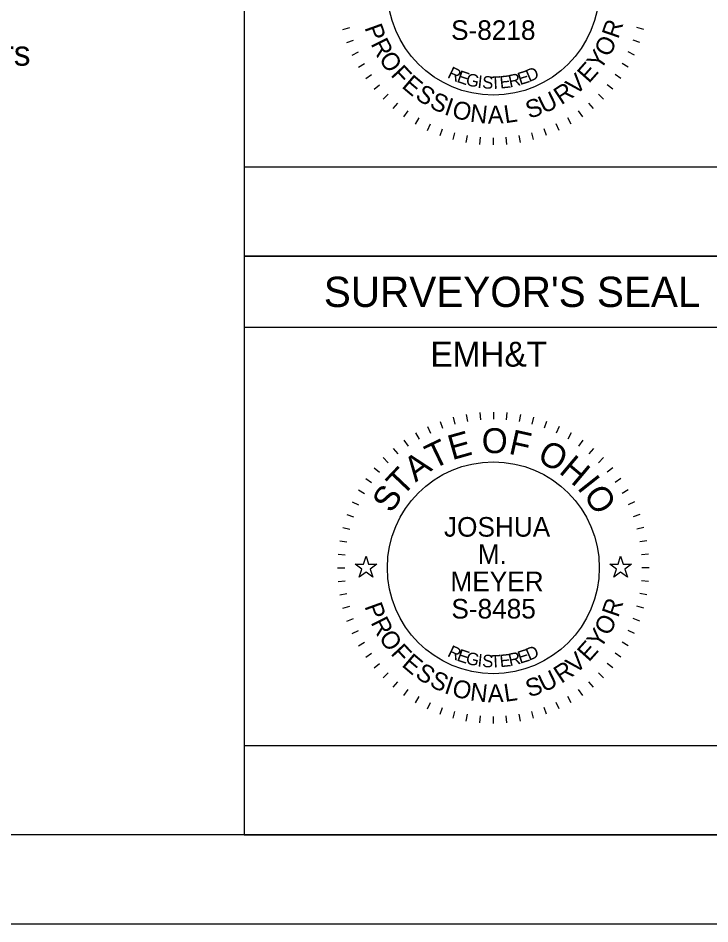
# Model space of a CAD drawing. Extents: x 0 to 34, y -5.4 to 22.
# Drawn here: x 27.93 to 31.82, y 0 to 5.09 of the extents above; entities that cross this region are included whole.
import ezdxf

# ---------------------------------------------------------------- set-up
doc = ezdxf.new("R2010")
doc.units = 0
for name, color, linetype in [('Default', 7, 'Continuous'), ('SH_Border', 7, 'Continuous'), ('SH_Cut_Line', 7, 'Continuous'), ('SH_Data', 7, 'Continuous'), ('SH_Text', 7, 'Continuous')]:
    doc.layers.add(name, color=color, linetype=linetype)

msp = doc.modelspace()

# ---------------------------------------------------------------- linework, layer by layer
at = {"layer": 'Default'}
for points in [[(29.8236, 2.02), (29.8705, 2.02), (29.885, 2.0645), (29.8995, 2.02), (29.9464, 2.02), (29.9085, 1.9924), (29.923, 1.9478), (29.885, 1.9754), (29.847, 1.9478), (29.8615, 1.9924)], [(31.2536, 2.02), (31.3005, 2.02), (31.315, 2.0645), (31.3295, 2.02), (31.3764, 2.02), (31.3385, 1.9924), (31.353, 1.9478), (31.315, 1.9754), (31.277, 1.9478), (31.2915, 1.9924)]]:
    msp.add_lwpolyline(points, close=True, dxfattribs=at)
at = {"layer": 'SH_Border'}
msp.add_lwpolyline([(1.5, 21.5), (33.5, 21.5), (33.5, 0.5), (1.5, 0.5)], close=True, dxfattribs=at)
at = {"layer": 'SH_Cut_Line'}
msp.add_lwpolyline([(0, 0), (34, 0), (34, 22), (0, 22)], close=True, dxfattribs=at)
at = {"layer": 'SH_Data'}
for p, q in [((29.2, 7), (29.2, 3.75)), ((29.7548, 5.0235), (29.7935, 5.0339)), ((31.4452, 5.0235), (31.4065, 5.0339)), ((29.7778, 4.9507), (29.8154, 4.9644)), ((31.4222, 4.9507), (31.3846, 4.9644)), ((29.807, 4.8802), (29.8432, 4.8971)), ((31.393, 4.8802), (31.3568, 4.8971)), ((29.8422, 4.8125), (29.8769, 4.8325)), ((31.3578, 4.8125), (31.3231, 4.8325)), ((29.8832, 4.7481), (29.916, 4.7711)), ((31.3168, 4.7481), (31.284, 4.7711)), ((29.9297, 4.6876), (29.9604, 4.7133)), ((31.2703, 4.6876), (31.2396, 4.7133)), ((29.9813, 4.6313), (30.0096, 4.6596)), ((31.2187, 4.6313), (31.1904, 4.6596)), ((30.0376, 4.5797), (30.0633, 4.6104)), ((31.1624, 4.5797), (31.1367, 4.6104)), ((30.0981, 4.5332), (30.1211, 4.566)), ((31.1019, 4.5332), (31.0789, 4.566)), ((30.1625, 4.4922), (30.1825, 4.5269)), ((30.2302, 4.457), (30.2471, 4.4932)), ((30.9698, 4.457), (30.9529, 4.4932)), ((31.0375, 4.4922), (31.0175, 4.5269)), ((30.3007, 4.4278), (30.3144, 4.4654)), ((30.3735, 4.4048), (30.3839, 4.4435)), ((30.4481, 4.3883), (30.455, 4.4277)), ((30.7519, 4.3883), (30.745, 4.4277)), ((30.8265, 4.4048), (30.8161, 4.4435)), ((30.8993, 4.4278), (30.8856, 4.4654)), ((30.5237, 4.3783), (30.5272, 4.4182)), ((30.6, 4.375), (30.6, 4.415)), ((30.6763, 4.3783), (30.6728, 4.4182)), ((32, 3.75), (29.2, 3.75)), ((29.2, 3.75), (29.2, 0.5)), ((32, 3.75), (29.2, 3.75)), ((32, 3.35), (29.2, 3.35)), ((30.4481, 2.8617), (30.455, 2.8223)), ((30.5237, 2.8717), (30.5272, 2.8318)), ((30.6, 2.875), (30.6, 2.835)), ((30.6763, 2.8717), (30.6728, 2.8318)), ((30.7519, 2.8617), (30.745, 2.8223)), ((30.3007, 2.8222), (30.3144, 2.7846)), ((30.3735, 2.8452), (30.3839, 2.8065)), ((30.8265, 2.8452), (30.8161, 2.8065)), ((30.8993, 2.8222), (30.8856, 2.7846)), ((30.1625, 2.7578), (30.1825, 2.7231)), ((30.2302, 2.793), (30.2471, 2.7568)), ((30.9698, 2.793), (30.9529, 2.7568)), ((31.0375, 2.7578), (31.0175, 2.7231)), ((30.0981, 2.7168), (30.1211, 2.684)), ((31.1019, 2.7168), (31.0789, 2.684)), ((30.0376, 2.6703), (30.0633, 2.6396)), ((31.1624, 2.6703), (31.1367, 2.6396)), ((29.9813, 2.6187), (30.0096, 2.5904)), ((31.2187, 2.6187), (31.1904, 2.5904)), ((29.9297, 2.5624), (29.9604, 2.5367)), ((31.2703, 2.5624), (31.2396, 2.5367)), ((29.8832, 2.5019), (29.916, 2.4789)), ((31.3168, 2.5019), (31.284, 2.4789)), ((29.8422, 2.4375), (29.8769, 2.4175)), ((31.3578, 2.4375), (31.3231, 2.4175)), ((29.807, 2.3698), (29.8432, 2.3529)), ((31.393, 2.3698), (31.3568, 2.3529)), ((29.7778, 2.2993), (29.8154, 2.2856)), ((31.4222, 2.2993), (31.3846, 2.2856)), ((29.7548, 2.2265), (29.7935, 2.2161)), ((31.4452, 2.2265), (31.4065, 2.2161)), ((29.7383, 2.1519), (29.7777, 2.145)), ((31.4617, 2.1519), (31.4223, 2.145)), ((29.7283, 2.0763), (29.7682, 2.0728)), ((31.4717, 2.0763), (31.4318, 2.0728)), ((29.725, 2), (29.765, 2)), ((31.475, 2), (31.435, 2)), ((29.7283, 1.9237), (29.7682, 1.9272)), ((31.4717, 1.9237), (31.4318, 1.9272)), ((29.7383, 1.8481), (29.7777, 1.855)), ((31.4617, 1.8481), (31.4223, 1.855)), ((29.7548, 1.7735), (29.7935, 1.7839)), ((31.4452, 1.7735), (31.4065, 1.7839)), ((29.7778, 1.7007), (29.8154, 1.7144)), ((31.4222, 1.7007), (31.3846, 1.7144)), ((29.807, 1.6302), (29.8432, 1.6471)), ((31.393, 1.6302), (31.3568, 1.6471)), ((29.8422, 1.5625), (29.8769, 1.5825)), ((31.3578, 1.5625), (31.3231, 1.5825)), ((29.8832, 1.4981), (29.916, 1.5211)), ((31.3168, 1.4981), (31.284, 1.5211)), ((29.9297, 1.4376), (29.9604, 1.4633)), ((31.2703, 1.4376), (31.2396, 1.4633)), ((29.9813, 1.3813), (30.0096, 1.4096)), ((31.2187, 1.3813), (31.1904, 1.4096)), ((30.0376, 1.3297), (30.0633, 1.3604)), ((31.1624, 1.3297), (31.1367, 1.3604)), ((30.0981, 1.2832), (30.1211, 1.316)), ((30.1625, 1.2422), (30.1825, 1.2769)), ((31.0375, 1.2422), (31.0175, 1.2769)), ((31.1019, 1.2832), (31.0789, 1.316)), ((30.2302, 1.207), (30.2471, 1.2432)), ((30.9698, 1.207), (30.9529, 1.2432)), ((30.3007, 1.1778), (30.3144, 1.2154)), ((30.3735, 1.1548), (30.3839, 1.1935)), ((30.4481, 1.1383), (30.455, 1.1777)), ((30.7519, 1.1383), (30.745, 1.1777)), ((30.8265, 1.1548), (30.8161, 1.1935)), ((30.8993, 1.1778), (30.8856, 1.2154)), ((30.5237, 1.1283), (30.5272, 1.1682)), ((30.6, 1.125), (30.6, 1.165)), ((30.6763, 1.1283), (30.6728, 1.1682)), ((32, 0.5), (29.2, 0.5)), ((32, 0.5), (29.2, 0.5))]:
    msp.add_line(p, q, dxfattribs=at)
for points in [[(32, 3.75), (32, 4.25), (29.2, 4.25), (29.2, 3.75)], [(32, 0.5), (32, 1), (29.2, 1), (29.2, 0.5)]]:
    msp.add_lwpolyline(points, close=True, dxfattribs=at)
for centre in [(30.6, 5.25), (30.6, 2)]:
    msp.add_circle(centre, 0.595, dxfattribs=at)

# ---------------------------------------------------------------- texts
for s, height, rotation, p in [('P', 0.1, 289.7431, (29.8753, 5.0341)), ('R', 0.1, 70.983, (31.3009, 4.9667)), ('R', 0.1, 296.9802, (29.9093, 4.9427)), ('O', 0.1, 62.7428, (31.2501, 4.8633)), ('O', 0.1, 304.7158, (29.9532, 4.8579)), ('Y', 0.1, 55.5058, (31.2, 4.79)), ('E', 0.1, 48.2687, (31.1366, 4.7173)), ('F', 0.1, 312.956, (30.0192, 4.7658)), ('R', 0.07, 334.487, (30.3375, 4.7551)), ('E', 0.07, 341.04, (30.3906, 4.7301)), ('E', 0.07, 17.6836, (30.7498, 4.7102)), ('D', 0.07, 23.3052, (30.801, 4.727)), ('V', 0.1, 41.0316, (31.0615, 4.6507)), ('E', 0.1, 319.6885, (30.0808, 4.7004)), ('G', 0.07, 347.4752, (30.4414, 4.7118)), ('I', 0.07, 353.7858, (30.5091, 4.6968)), ('S', 0.07, 356.8926, (30.5358, 4.6929)), ('T', 0.07, 3.0061, (30.5857, 4.6887)), ('E', 0.07, 6.0117, (30.6389, 4.6912)), ('R', 0.07, 11.9184, (30.6925, 4.6974)), ('S', 0.1, 326.9255, (30.1554, 4.6385)), ('R', 0.1, 33.296, (30.9815, 4.5973)), ('S', 0.1, 334.1626, (30.236, 4.5874)), ('I', 0.1, 341.3997, (30.3191, 4.5479)), ('S', 0.1, 18.3234, (30.8005, 4.5211)), ('U', 0.1, 25.5604, (30.8833, 4.5486)), ('O', 0.1, 345.1351, (30.3618, 4.5321)), ('N', 0.1, 353.3752, (30.466, 4.5055)), ('A', 0.1, 1.1108, (30.5692, 4.4943)), ('L', 0.1, 8.3479, (30.6664, 4.4967)), ('E', 0.14, 15.7571, (30.3684, 2.6038)), ('O', 0.14, 359.7812, (30.5347, 2.6443)), ('F', 0.14, 347.4362, (30.6811, 2.6417)), ('T', 0.14, 25.7167, (30.2616, 2.5518)), ('O', 0.14, 332.2586, (30.8398, 2.6015)), ('A', 0.14, 36.4747, (30.1634, 2.4781)), ('H', 0.14, 319.9136, (30.9632, 2.5361)), ('T', 0.14, 46.4344, (30.0883, 2.3964)), ('I', 0.14, 308.367, (31.0665, 2.4483)), ('S', 0.14, 57.1924, (30.0281, 2.3014)), ('O', 0.14, 303.1491, (31.1021, 2.4089)), ('P', 0.1, 289.7431, (29.8753, 1.7841)), ('R', 0.1, 70.983, (31.3009, 1.7167)), ('O', 0.1, 62.7428, (31.2501, 1.6133)), ('R', 0.1, 296.9802, (29.9093, 1.6927)), ('O', 0.1, 304.7158, (29.9532, 1.6079)), ('Y', 0.1, 55.5058, (31.2, 1.54)), ('E', 0.1, 48.2687, (31.1366, 1.4673)), ('F', 0.1, 312.956, (30.0192, 1.5158)), ('R', 0.07, 334.487, (30.3375, 1.5051)), ('E', 0.07, 341.04, (30.3906, 1.4801)), ('G', 0.07, 347.4752, (30.4414, 1.4618)), ('E', 0.07, 17.6836, (30.7498, 1.4602)), ('D', 0.07, 23.3052, (30.801, 1.477)), ('V', 0.1, 41.0316, (31.0615, 1.4007)), ('E', 0.1, 319.6885, (30.0808, 1.4504)), ('I', 0.07, 353.7858, (30.5091, 1.4468)), ('S', 0.07, 356.8926, (30.5358, 1.4429)), ('T', 0.07, 3.0061, (30.5857, 1.4387)), ('E', 0.07, 6.0117, (30.6389, 1.4412)), ('R', 0.07, 11.9184, (30.6925, 1.4474)), ('S', 0.1, 326.9255, (30.1554, 1.3885)), ('U', 0.1, 25.5604, (30.8833, 1.2986)), ('R', 0.1, 33.296, (30.9815, 1.3473)), ('S', 0.1, 334.1626, (30.236, 1.3374)), ('I', 0.1, 341.3997, (30.3191, 1.2979)), ('S', 0.1, 18.3234, (30.8005, 1.2711)), ('O', 0.1, 345.1351, (30.3618, 1.2821)), ('N', 0.1, 353.3752, (30.466, 1.2555)), ('A', 0.1, 1.1108, (30.5692, 1.2443)), ('L', 0.1, 8.3479, (30.6664, 1.2467))]:
    msp.add_text(s, height=height, rotation=rotation, dxfattribs=at).set_placement(p)
for s, height, p in [('S-8218', 0.11, (30.3626, 4.9651)), ("SURVEYOR'S SEAL", 0.17, (29.6478, 3.465)), ('EMH&T', 0.14, (30.2465, 3.13)), ('JOSHUA', 0.11, (30.3228, 2.1749)), ('M.', 0.11, (30.5126, 2.0216)), ('MEYER', 0.11, (30.3592, 1.8684)), ('S-8485', 0.11, (30.3643, 1.7151))]:
    msp.add_text(s, height=height, dxfattribs=at).set_placement(p)
at = {"layer": 'SH_Text'}
msp.add_text('centerline of Right of Way and the existing Right of Way limits as necessary for the property takes contained herein. See the Survey Parameters ', height=0.14, dxfattribs=at).set_placement((16.0751, 4.8203))

doc.saveas('drawing.dxf')
